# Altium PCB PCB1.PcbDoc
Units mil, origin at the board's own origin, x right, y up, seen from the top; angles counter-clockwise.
Board outline 2185.43 x 2030.28 mil, 2 copper layers (Top Layer, Bottom Layer); 55 components, 46 nets, 190 pads, 15 vias.
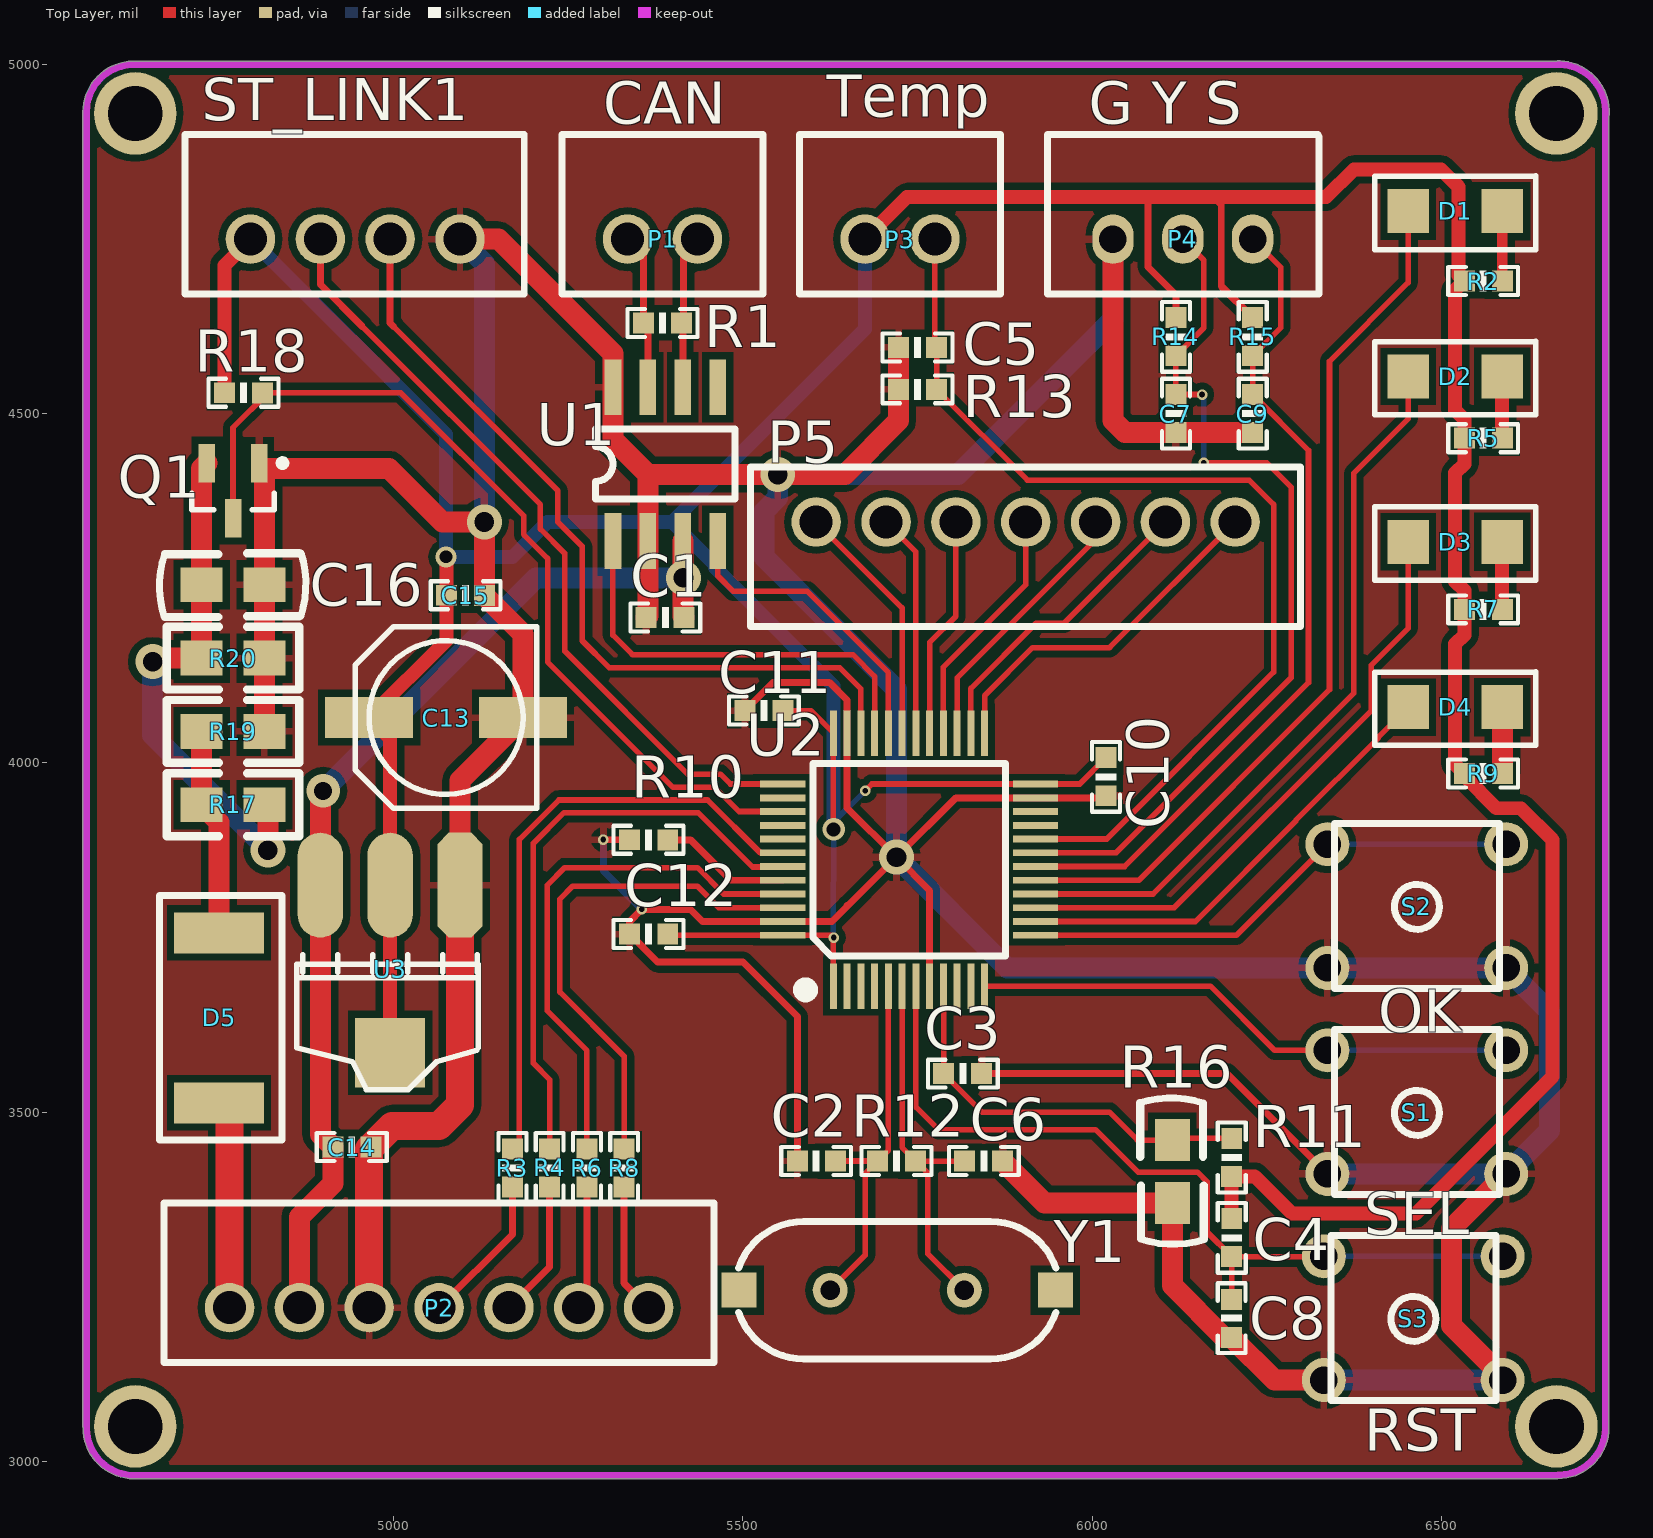
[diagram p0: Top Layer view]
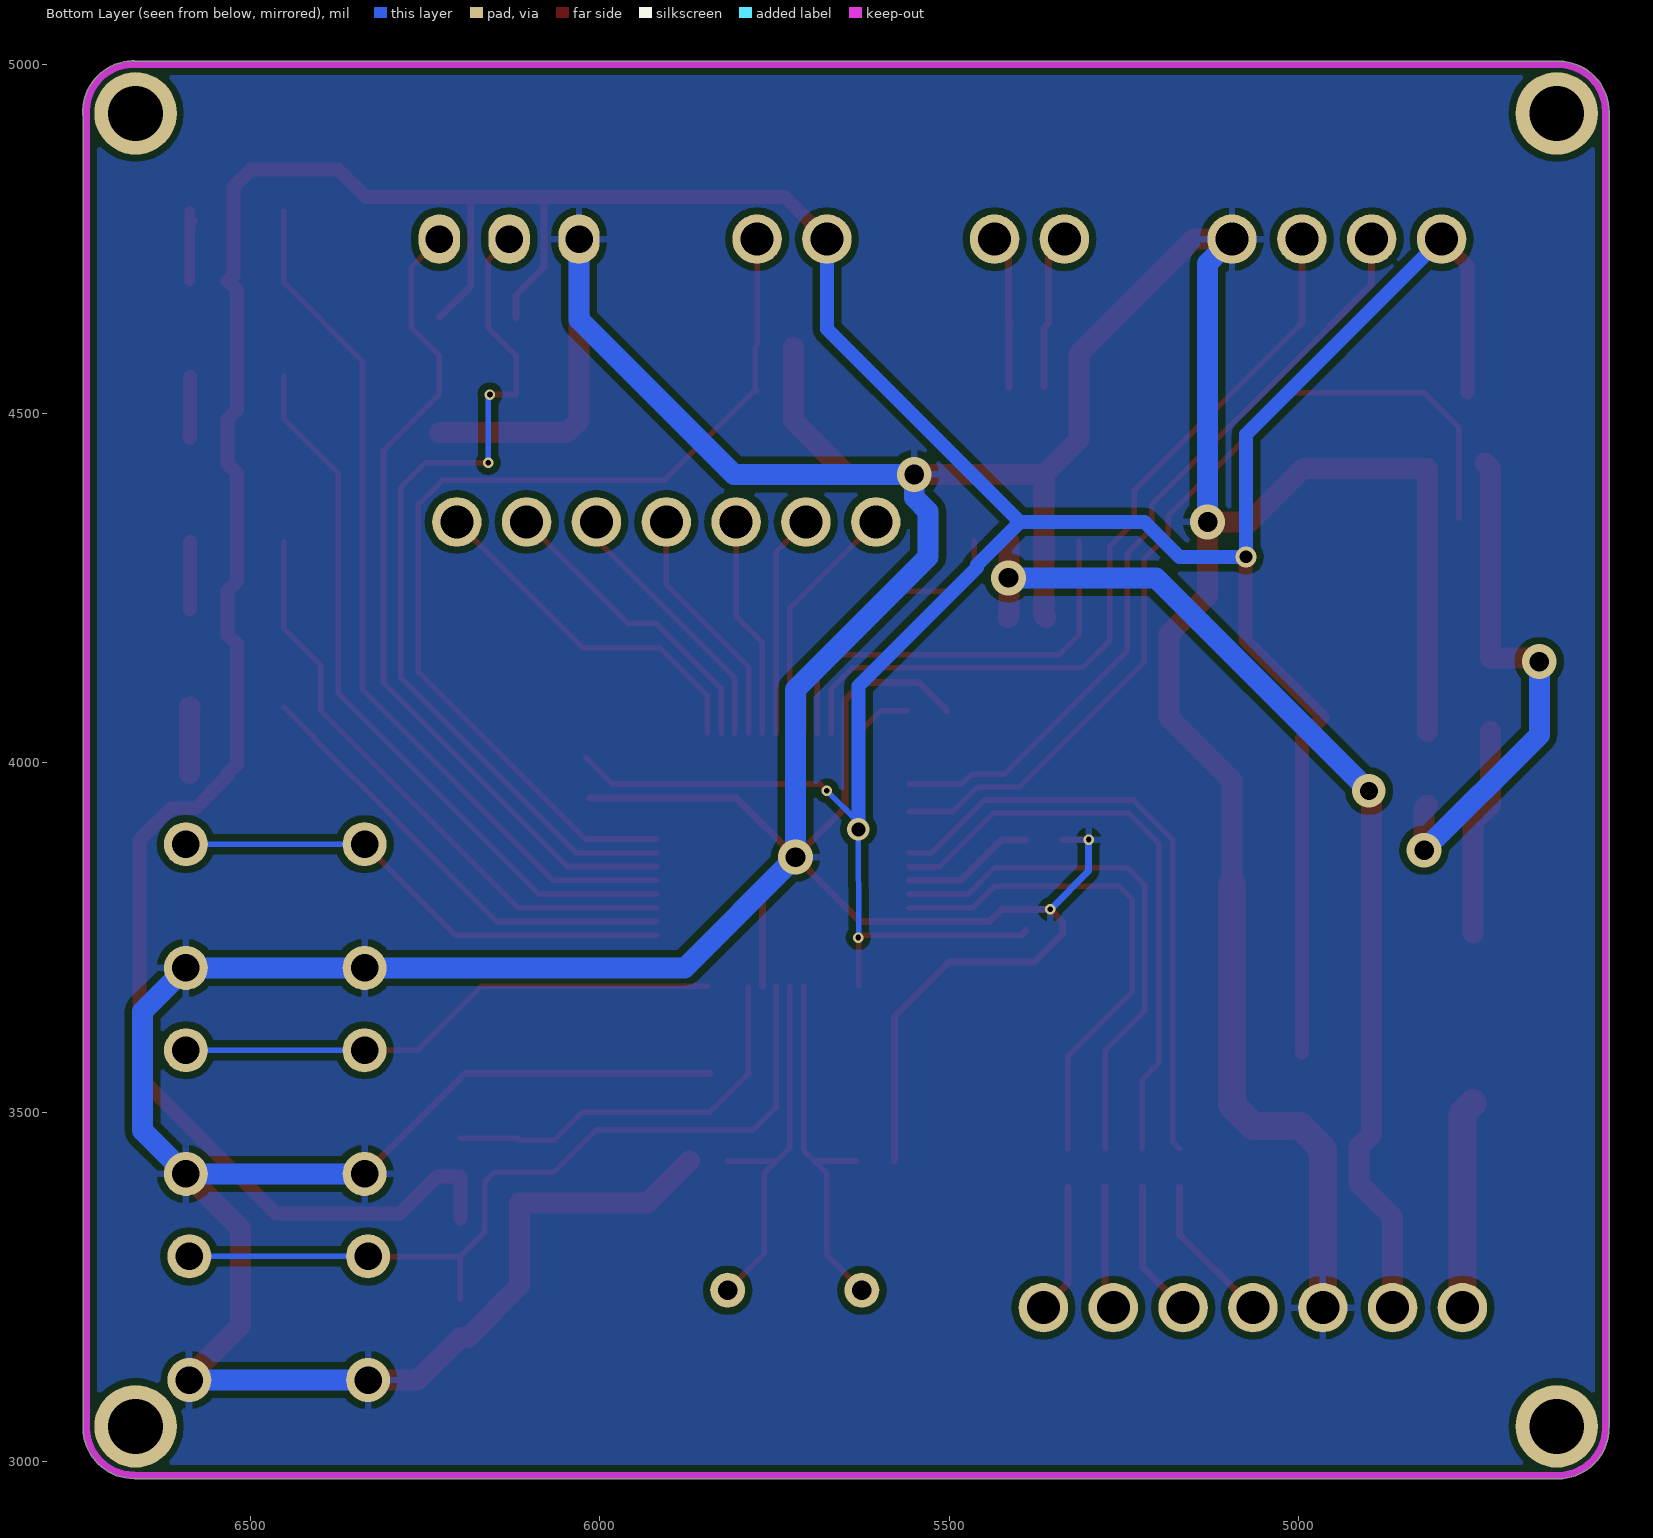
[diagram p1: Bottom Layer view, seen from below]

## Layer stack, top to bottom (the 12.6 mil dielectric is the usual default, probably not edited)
Top Layer: signal copper 1.4
Dielectric: dielectric 12.6, FR-4, Dk 4.8
Bottom Layer: signal copper 1.4

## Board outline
4555.22,3047.88 ccw(c4628.12,3047.88) 4627.86,2974.99 ccw(c4627.88,2980) 4628.94,2975.1 ccw(c4630,2980) 4630,2974.99 6665,2974.99 ccw(c6665,2980) 6666.6,2975.25 ccw(c6667.12,2980.24) 6667.12,2975.22 ccw(c6667.12,3048.12) 6740.01,3047.86 ccw(c6735,3047.88) 6740.01,3047.88 ccw(c6735,3047.88) 6739.9,3048.94 ccw(c6735,3050) 6740.02,3050 6740.02,4924.73 ccw(c6667.52,4932.36) 6740.42,4932.36 ccw(c6667.52,4932.36) 6740.02,4939.99 6740.02,4940 ccw(c6735,4940) 6739.89,4941.13 ccw(c6667.52,4932.36) 6676.85,5004.66 ccw(c6675,5000) 6675,5005.02 6673.5,5005.02 ccw(c6667.52,4932.36) 6667.77,5005.26 ccw(c6667.75,5000.25) 6666.21,5005.02 4627.88,5005.02 ccw(c4627.88,5000) 4626.31,5004.76 ccw(c4627.88,4931.88) 4554.99,4932.14 ccw(c4560,4932.12) 4554.99,4932.01 ccw(c4560,4931.88) 4554.98,4931.88 4554.98,3050 ccw(c4560,3050) 4555.25,3048.4 ccw(c4560.24,3047.88)

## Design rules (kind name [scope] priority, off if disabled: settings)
Clearance Clearance_1 [InPolygon] p1: gap=10
Clearance Clearance_U2 [InComponent('U2')] p2: gap=6
Clearance [All] p3: gap=10
ComponentClearance [All] p1 off: gap=10 collisioncheckmode=3 verticalgap=10 showdistances=FALSE
MinimumSolderMaskSliver [All] p1 off: minsoldermaskwidth=10
PolygonConnect [All] p1: connectstyle=Relief reliefconductorwidth=10 reliefentries=4 polygonreliefangle="90 Angle" airgapwidth=10
RoutingVias [All] p1: holewidth=28 width=50 viastyle="Through Hole" minholewidth=28 minwidth=50 maxholewidth=28 maxwidth=50
SilkToSilkClearance [All] p1 off: silktosilkclearance=10
SilkToSolderMaskClearance [IsPad] p1 off: minsilkscreentomaskgap=10 clearancetoexposedcopper=TRUE
SolderMaskExpansion [All] p1: expansion=4
Width [All] p1: maxlimit=50 minlimit=8 preferedwidth=10
24 further rules are at their usual default settings.

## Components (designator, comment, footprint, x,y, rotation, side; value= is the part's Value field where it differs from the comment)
C1 "Cap" 0603P 5389,4208 r180 top
C2 "Cap" 0603P 5605,3430 r0 top
C3 "Cap" 0603P 5815,3555 r180 top
C4 "Cap" 0805_C 6115,3370 r90 top
C5 "Cap" 0603P 5750,4595 r0 top
C6 "Cap" 0603P 5845,3430 r180 top
C7 "Cap" 0603P 6120,4500 r90 top
C8 "Cap" 0603P 6200,3205 r270 top
C9 "Cap" 0603P 6230,4500 r90 top
C10 "Cap" 0603P 6020,3980 r90 top
C11 "Cap" 0603P 5530,4075 r0 top
C12 "Cap" 0603P 5365,3755 r0 top
C13 "Cap Pol1" CC6.56.5 5075,4065 r0 top
C14 "Cap" 0603P 4940,3450 r0 top
C15 "Cap" 0603P 5103,4240 r180 top
C16 "Cap" 0805_C 4815,4255 r180 top
D1 "1206" 1206 6520,4790 r180 top
D2 "1206" 1206 6520,4553.33 r180 top
D3 "1206" 1206 6520,4316.67 r180 top
D4 "1206" 1206 6520,4080 r180 top
D5 "1N4007" DO-214AB 4750,3635 r90 top
P1 "CAN" 2.54_2P 5335,4750 r0 top
P2 "" 2.54_7P 4765,3220 r0 top
P3 "Temp" 2.54_2P 5675,4750 r0 top
P4 "G Y S" 2.54_3P 6030,4750 r0 top
P5 "" 2.54_7P 6205,4345 r180 top
Q1 "S9014" SOT23-3 4770,4390 r270 top
R1 "Res2" 0603P 5385,4630 r180 top
R2 "Res2" 0603P 6560,4690 r0 top
R3 "Res2" 0603P 5170,3420 r90 top
R4 "Res2" 0603P 5223.33,3420 r90 top
R5 "Res2" 0603P 6560,4465 r0 top
R6 "Res2" 0603P 5276.67,3420 r90 top
R7 "Res2" 0603P 6560,4220 r0 top
R8 "Res2" 0603P 5330,3420 r90 top
R9 "Res2" 0603P 6560,3985 r0 top
R10 "Res2" 0603P 5365,3890 r0 top
R11 "Res2" 0603P 6200,3435 r90 top
R12 "Res2" 0603P 5720,3430 r0 top
R13 "Res2" 0603P 5750,4535 r0 top
R14 "Res2" 0603P 6120,4610 r90 top
R15 "Res2" 0603P 6230,4610 r90 top
R16 "Res2" 0603P 6200,3320 r90 top
R17 "Res2" 0805_R 4815,3940 r180 top
R18 "Res2" 0603P 4785,4530 r180 top
R19 "Res2" 0805_R 4815,4045 r180 top
R20 "Res2" 0805_R 4815,4150 r180 top
S1 "SEL" "KEY 6*6" 6465,3500 r180 top
S2 "OK" "KEY 6*6" 6465,3795 r180 top
S3 "RST" "KEY 6*6" 6460,3205 r180 top
ST_LINK1 "Header 4" 2.54_4P 4795,4750 r0 top
U1 "TJA1050" SO-8 5314,4318 r90 top
U2 "STM32F103C8T6" LQFP48S 5630,3680 r90 top
U3 "AMS1117-3.3" AMS1117 5095,3825 r180 top
Y1 "8M" XTAL_US 5625,3245 r0 top

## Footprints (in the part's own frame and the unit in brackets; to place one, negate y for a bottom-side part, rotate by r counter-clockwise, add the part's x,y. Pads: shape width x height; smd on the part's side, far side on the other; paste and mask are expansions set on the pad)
2.54_2P [mm]
  round 1.8 hole 1.2: 1(0,0) 2(2.54,0)
  silkscreen extent -2.38,-2 4.92,3.8
2.54_3P [mm]
  oval 1.5x1.8 hole 1: 1(0,0) 2(2.54,0) 3(5.08,0)
  silkscreen extent -2.38,-2 7.49,3.8
2.54_4P [mm]
  round 1.8 hole 1.2: 1(0,0) 2(2.54,0) 3(5.08,0) 4(7.62,0)
  silkscreen extent -2.38,-2 9.96,3.8
2.54_7P [mm]
  round 1.8 hole 1.2: 1(0,0) 2(2.54,0) 3(5.08,0) 4(7.62,0) 5(10.16,0) 6(12.7,0) 7(15.24,0)
  silkscreen extent -2.38,-2 17.62,3.8
0603P [mil]
  rect 30x30 smd: 1(-27,0) 2(27.5,-0.06)
  silkscreen extent -50,-20 50,20
0805_C [mil]
  rect 60x50 smd: 1(0,-0.06) 2(90,-0.06)
  silkscreen extent -59,-46 150,47
0805_R [mil]
  rect 60x50 smd: 1(0,-0.06) 2(90,-0.06)
  silkscreen extent -50,-45 140,45
1206 [mm]
  rect 1.52x1.6 smd: 1(-1.71,0) 2(1.71,0)
  silkscreen extent -2.92,-1.28 2.92,1.4
AMS1117 [mil]
  oct 65x150 smd: 1(0.03,-0.06)
  oval 65x150 smd: 2(100.03,-0.06) 3(200.03,-0.06)
  rect 100x100 smd: 4(100.03,239.94)
  silkscreen extent -26,100 234,293
CC6.56.5 [mm]
  rect 3.2x1.5 smd: 1(-2.794,0) 2(2.8,0)
  silkscreen extent -3.3,-3.3 3.3,3.3
DO-214AB [mm]
  rect 1.49x3.27 smd: 1(-3.09,0) 2(3.09,0)
  silkscreen extent -4.44,-2.29 4.44,2.16
"KEY 6*6" [mm]
  round 1.6 hole 1: 1(-3.25,2.25) 1(3.25,2.25) 2(-3.25,-2.25) 2(3.25,-2.25)
  silkscreen extent -3,-3 3,3
LQFP48S [mil] "DPIN-0.5"
  rect 65x10 smd: 1(0.42,0.29) 2(0.42,-19.39) 3(0.42,-39.08) 4(0.42,-58.76) 5(0.42,-78.45) 6(0.42,-98.13) 7(0.42,-117.82) 8(0.42,-137.5) 9(0.42,-157.19) 10(0.42,-176.87) 11(0.42,-196.56) 12(0.42,-216.24) 25(362.63,-216.24) 26(362.63,-196.56) 27(362.63,-176.87) 28(362.63,-157.19) 29(362.63,-137.5) 30(362.63,-117.82) 31(362.63,-98.13) 32(362.63,-78.45) 33(362.63,-58.76) 34(362.63,-39.08) 35(362.63,-19.39) 36(362.63,0.29)
  rect 10x65 smd: 13(73.26,-289.08) 14(92.94,-289.08) 15(112.63,-289.08) 16(132.31,-289.08) 17(152,-289.08) 18(171.68,-289.08) 19(191.37,-289.08) 20(211.05,-289.08) 21(230.74,-289.08) 22(250.42,-289.08) 23(270.11,-289.08) 24(289.79,-289.08) 37(289.79,73.13) 38(270.11,73.13) 39(250.42,73.13) 40(230.74,73.13) 41(211.05,73.13) 42(191.37,73.13) 43(171.68,73.13) 44(152,73.13) 45(132.31,73.13) 46(112.63,73.13) 47(92.94,73.13) 48(73.26,73.13)
  silkscreen extent -10,-246 319,46
SO-8 [mil]
  rect 80x24 smd: 1(0,0) 2(0,-50) 3(0,-100) 4(0,-150) 5(220,-150) 6(220,-100) 7(220,-50) 8(220,0)
  silkscreen extent 60,-175 160,25, body extent -11,-172 225,21, height 64
SOT23-3 [mm] "SOT23, 3-Leads, Body 2.90x2.45mm, Pitch 0.95mm, IPC Medium Density"
  rect 1.4x0.6 smd: 1(-1,0.95) 2(-1,-0.95) 3(1,0)
  silkscreen extent -1.12,-1.5 0.7,1.93, body extent -0.7,-1.5 0.7,1.5, height 1
XTAL_US [mil]
  round 50 hole 28: 1(0,0) 2(192.13,0)
  rect 50x50 smd: ""(-130.32,0) ""(322.44,0)
  silkscreen extent -131,-98 323,98

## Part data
C1 C2 C3 C4 C5 C6 C7 C8 C9 C10 C11 C12 C14 C15 C16: "Capacitor"
C13: "Polarized Capacitor (Radial)"
D1 D2 D3 D4: library part LED0, "Typical INFRARED GaAs LED"
D5: library part "Diode 1N4007", "1 Amp General Purpose Rectifier"
P1 P3: library part "Header 2", "Header, 2-Pin"
P2 P5: library part "Header 7", "Header, 7-Pin"
P4: library part "Header 3", "Header, 3-Pin"
Q1: library part 2N3904, "NPN General Purpose Amplifier"
R1 R2 R3 R4 R5 R6 R7 R8 R9 R10 R11 R12 R13 R14 R15 R16 R17 R18 R19 R20: "Resistor"
S1 S2 S3: library part SW-PB, "Switch"
ST_LINK1: "Header, 4-Pin"
U3: library part AMS1117
Y1: library part XTAL, "Crystal Oscillator"

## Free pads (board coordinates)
  round 118.11 hole 78.74: 0(4630,3050) 0(4630,4930) 0(6665,3050) 0(6665,4930)

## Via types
v1: diameter 15, hole 8, Top Layer to Bottom Layer, 6 vias
v2: diameter 50, hole 28, Top Layer to Bottom Layer, 6 vias
v3: diameter 32, hole 20, Top Layer to Bottom Layer, 1 vias
v4: diameter 48, hole 26, Top Layer to Bottom Layer, 1 vias
v5: diameter 30, hole 18, Top Layer to Bottom Layer, 1 vias

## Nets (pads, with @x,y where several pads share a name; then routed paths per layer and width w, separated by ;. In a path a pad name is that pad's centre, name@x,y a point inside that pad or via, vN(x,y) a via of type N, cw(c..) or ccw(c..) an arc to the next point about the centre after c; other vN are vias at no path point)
3V3: C10.2 C11.2 C12.2 C13.1 C15.2 P3.1 R2.1 R5.1 R7.1 R9.1 R11.1 R14.2 R15.2 R16.2 R18.2 ST_LINK1.1 U2.1 U2.24 U2.36 U2.48 U3.2 U3.4 | length 7379.3
  Top Layer w8: C12.2@5396.68,3753.26 U2.48 5626.74,3753.26 v1(5630,3750) 5629.71,3749.71 U2.1 ; C11.2@5560,4074.94 5597.4,4074.94 U2.36 v3@5629.71,3905 ; v1(5675,3960) 5684.79,3969.79 U2.24 5982.36,3969.79 C10.2
  Top Layer w10: C12.2@5390,3759.94 C12.2@5396.68,3753.26 ; 6080,4810 6080,4710.13 6120.06,4670.06 R14.2 ; 6175,4810 6185,4800 6185,4682.56 R15.2
  Top Layer w20: R18.2 4757.5,4712.5 ST_LINK1.1 ; U3.4 U3.2 4994.97,4035.03 C13.1 5075.5,4175.5 C15.2 5075.5,4294.44 v5(5075,4294.94) ; P3.1 5735,4810 6080,4810 6175,4810 6335,4810 6375,4850 6500,4850 6525,4825 6525,4698 R2.1 6520,4677 6520,4505 6533,4492 R5.1 6533,4428 6520,4415 6520,4260 6533,4247 R7.1 6533,4183 6520,4170 6520,3998 R9.1 6533,3981.15 6579.07,3935.08 6614.28,3935.08 6659.36,3890 6659.36,3550.65 6463.71,3355 6286,3355 6233,3408 R11.1 6200,3347.56 R16.2
  Bottom Layer w8: v1@5629.71,3755 v3(5630,3905) ; v3@5630,3915 v1(5675,3960)
  Bottom Layer w20: ST_LINK1.1 5075,4470 v5@5075,4295 ; v5(5075,4294.94) 5169.94,4294.94 5220,4345 5398.64,4345 ; v3(5630,3905) 5630,3915 5630,4110 5460,4280 5460,4283.64 5398.64,4345 ; P3.1 5675,4621.36 5398.64,4345
5V0: C1.1 C14.1 P2.2 U1.3 U3.3 | length 1523.2
  Top Layer w30: P2.2 4865,3350 4913,3398 C14.1 4894.97,3468.03 U3.3 4894.97,3955.9 v4(4899,3959.94) ; U1.3 5414,4210 C1.1
  Bottom Layer w30: v4@4898,3960 v4@4899.06,3960 ; v4(4899,3959.94) v4@4899.06,3960 ; v2(5415,4265) 5204.06,4265 v4@4899.06,3960
A: P5.1 U2.25 | length 515.4
  Top Layer w8: U2.25 5846.24,4096.24 5915,4165 6025,4165 P5.1
B: P5.2 U2.26 | length 441.1
  Top Layer w8: U2.26 5826.56,4106.56 5920,4200 5960,4200 P5.2
C: P5.3 U2.27 | length 384.4
  Top Layer w8: U2.27 5806.87,4121.87 6005,4320 P5.3
CAN_RX: U1.4 U2.32 | length 438.7
  Top Layer w8: U1.4 5464,4268 5486,4246 5591.98,4246 5708.45,4129.53 U2.32
CAN_TX: U1.1 U2.33 | length 615.4
  Top Layer w8: U1.1 5314,4183 5342,4155 5657.53,4155 5688.76,4123.76 U2.33
CLK: P5.5 U2.29 | length 317.9
  Top Layer w8: U2.29 5767.5,4172.5 5805,4210 P5.5
D: R4.2 U2.43 | length 854.8
  Top Layer w8: R4.2 5223.4,3546.6 5200,3570 5200,3885 5243.94,3928.94 5436.06,3928.94 5514,3851 5556.19,3851 U2.43
DI: P5.7 U2.31 | length 353.4
  Top Layer w8: P5.7 5728.13,4221.87 U2.31
DJ: P2.6 R6.1 | length 177.8
  Top Layer w10: P2.6 5276.67,3231.67 R6.1
EN: P5.4 U2.28 | length 351.2
  Top Layer w8: U2.28 5787.19,4137.19 5905,4255 P5.4
F: R3.2 U2.42 | length 878.6
  Top Layer w8: R3.2 5180.06,3457.5 5180.06,3890.52 5236.48,3946.94 5449.35,3946.94 5524.92,3871.37 U2.42
FMQ: P2.4 R3.1 | length 216.5
  Top Layer w10: P2.4 5170,3325 R3.1
GND: C1.2 C2.1 C3.1 C4.1 C5.1 C6.1 C7.1 C8.2 C9.1 C10.1 C11.1 C12.1 C13.2 C14.2 C15.1 C16.1 P2.3 P4.1 Q1.1 R10.1 R13.1 R19.1 R20.1 S1.1 S2.1 S3.1 ST_LINK1.4 U1.2 U1.8 U2.8 U2.23 U2.35 U2.47 U3.1 | length 10858.3
  Top Layer w8: v2(5720,3865) v2@5730,3865
  Top Layer w10: v1(5300.29,3890.29) 5300.58,3890 R10.1 ; C11.1 5543,4115 5624.39,4115 5649.39,4090 U2.35 5649.39,3935.61 v2(5720,3865) ; C2.1 5578,3637 5500,3715 5378,3715 C12.1 5338,3773 5355,3790 5425,3790 5442.06,3772.94 U2.47 5627.94,3772.94 5650,3795 ; 5649.39,3795.61 5650,3795 ; U2.8 5767.5,3817.5 v2(5720,3865) ; C3.1 6193.46,3555 S1.1@6337.05,3411.42 ; C10.1@6014.89,3950.11 U2.23 5805.11,3950.11 v2(5720,3865) ; 5650,3795 v2(5720,3865)
  Top Layer w30: R19.1 R20.1 C16.1 4815,4421.77 4993.23,4421.77 5070,4345 v2(5130,4345) C15.1 5185.24,4184.76 C13.2 5094.97,3974.73 U3.1 ; ST_LINK1.4 5150,4750 5314,4586 U1.8 5314,4463 5364,4413 ; C1.2 5364,4210.56 U1.2 5364,4413 ; C5.1 R13.1 5723,4490 5646,4413 v2(5550,4413) 5364,4413 ; C6.1 5932,3370 C4.1 6115.06,3251.58 6189.14,3177.5 C8.2 6261.02,3116.42 S3.1@6332.05,3116.42 ; P4.1 6030,4490 6047,4473 C7.1 C9.1 ; S3.1@6592.95,3116.42 6515,3194.37 6515,3333.46 S1.1@6592.95,3411.42
  Top Layer w40: P2.3 4965,3447.44 C14.2 4997.56,3480 5065.06,3480 5094.97,3509.9 U3.1
  Bottom Layer w10: v1(5300.29,3890.29) 5300.29,3845 v1(5355,3790.29)
  Bottom Layer w30: ST_LINK1.4 5130,4715 v2(5130,4345) ; P4.1 6030,4635 5808,4413 v2(5550,4413) 5550,4380 5530,4360 5530,4295 5720,4105 v2(5720,3865) 5878.58,3706.42 6337.05,3706.42 6592.95,3706.42 6655,3644.37 6655,3473.46 6592.95,3411.42 S1.1@6337.05,3411.42 ; S3.1@6323.58,3116.42 6332.05,3116.42 6587.95,3116.42 S3.1@6592.95,3116.42
HH: P2.5 R4.1 | length 197.2
  Top Layer w10: P2.5 5223.33,3278.33 R4.1
KEY_OK: S2.2 U2.13 | length 727.9
  Top Layer w8: U2.13 6206.73,3753.26 S2.2@6337.05,3883.57
  Bottom Layer w8: S2.2@6337.05,3883.57 S2.2@6592.94,3883.57
KEY_SELECT: S1.2 U2.12 | length 784.8
  Top Layer w8: U2.12 6169.58,3680.42 6261.43,3588.57 S1.2@6337.05,3588.57
  Bottom Layer w8: S1.2@6337.05,3588.57 S1.2@6592.94,3588.57
LAT: P5.6 U2.30 | length 320.1
  Top Layer w8: P5.6 5747.82,4302.18 U2.30
LED0: D1.2 U2.17 | length 1265.7
  Top Layer w8: U2.17 6067,3832 6340,4105 6340,4575 6452.68,4687.68 D1.2
LED1: D2.2 U2.16 | length 1060.6
  Top Layer w8: U2.16 6087.31,3812.31 6375,4100 6375,4415 6452.68,4492.68 D2.2
LED2: D3.2 U2.15 | length 861.4
  Top Layer w8: U2.15 6117.63,3792.63 6400,4075 6400,4140 6452.68,4192.68 D3.2
LED3: D4.2 U2.14 | length 662.1
  Top Layer w8: U2.14 6147.94,3772.94 6291.55,3916.55 6291.55,3917.42 6410,4035.87 6410,4037.32 D4.2
M: R6.2 U2.45 | length 763.8
  Top Layer w8: R6.2 5276.73,3588.27 5220,3645 5220,3825 5245,3850 5435,3850 5472.69,3812.31 U2.45
NetC3_2: C3.2 C4.2 R11.2 U2.9 | length 577.3
  Top Layer w8: U2.9@5787.5,3679.37 C3.2 5842.56,3500 6025,3500 6065,3460 C4.2 6117.56,3462.5 R11.2
NetC16_2: C16.2 Q1.2 R17.1 R20.2 | length 760
  Top Layer w30: v2(4655,4145) 4660.06,4150.06 R20.2 C16.2 4725,4421.77 Q1.2 ; R17.1 4820,3935.06 v2(4820,3875)
  Bottom Layer w30: v2(4655,4145) 4655,4040 v2(4820,3875)
NetD1_1: D1.1 R2.2 | length 106.3
  Top Layer w15: D1.1@6582.94,4775.61 D1.1@6587.32,4780 ; D1.1 D1.1@6587.32,4780 ; R2.2 6587.32,4690.11 D1.1@6587.32,4780
NetD2_1: D2.1 R5.2 | length 88.5
  Top Layer w20: D2.1 6587.32,4465.11 R5.2
NetD3_1: D3.1 R7.2 | length 96.8
  Top Layer w20: D3.1 6587.32,4220.11 R7.2
NetD4_1: D4.1 R9.2 | length 95.1
  Top Layer w30: D4.1 6587.5,4079.82 R9.2
NetD5_2: D5.2 R17.2 R19.2 | length 298.8
  Top Layer w30: R19.2 R17.2 4750,3915.06 D5.2
NetP1_1: P1.1 R1.2 U1.7 | length 224
  Top Layer w10: P1.1 5357.5,4727.5 R1.2 5364,4623.56 U1.7
NetP1_2: P1.2 R1.1 U1.6 | length 222.4
  Top Layer w10: U1.6 5414,4628 R1.1 5415,4633 5415,4730 P1.2
NetR10_2: R10.2 U2.44 | length 190.9
  Top Layer w10: R10.2@5390,3889.94 5425.06,3889.94 5483,3832 U2.44
OSC_IN: C2.2 R12.1 U2.5 Y1.1 | length 530.5
  Top Layer w8: Y1.1 5675,3295 5675,3412 R12.1 ; C2.2 5632.56,3430 R12.1 ; U2.5 5708.45,3445.45 R12.1
OSC_OUT: C6.2 R12.2 U2.6 Y1.2 | length 542.3
  Top Layer w8: U2.6 5728.13,3449.3 R12.2 ; Y1.2 5765,3297.13 5765,3412.44 R12.2 ; C6.2 5817.37,3429.94 R12.2
R: R8.2 U2.46 | length 735
  Top Layer w8: R8.2 5330.06,3579.94 5238,3672 5238,3805.08 5256.46,3823.54 5434.77,3823.54 5465.69,3792.63 U2.46
RESET: C8.1 R16.1 S3.2 U2.7 | length 1205.5
  Top Layer w8: U2.7 5747.82,3507.18 5780,3475 6005,3475 6066,3414 6151,3414 6165,3400 6165,3328 R16.1 ; C8.1 R16.1 ; S3.2@6332.05,3293.57 6331.47,3293 R16.1
  Bottom Layer w8: S3.2@6332.05,3293.57 6337.05,3293.57 S3.2@6587.94,3293.57
RG: P2.7 R8.1 | length 187.5
  Top Layer w10: R8.1 5330,3255 P2.7
S: C9.2 P4.3 R15.1 U2.18 | length 1201.3
  Top Layer w8: U2.18 6046.68,3851.68 6310,4115 6310,4447.56 C9.2 6230,4527.56 R15.1 6270,4623 6270,4710 P4.3
TCK: ST_LINK1.2 U2.37 | length 1125.6
  Top Layer w8: 4955,4625 5210,4370 5210,4335 5245,4300 5245,4160 5421,3984 5467.87,3984 5482.08,3969.79 U2.37
  Top Layer w10: ST_LINK1.2 4895,4685 4955,4625
TEMP: C5.2 P3.2 R13.2 U2.20 | length 1444.5
  Top Layer w8: P3.2@5775,4745 5775,4597.44 C5.2 R13.2 ; R13.2@5775.57,4533 R13.2 ; U2.20 6021.05,3891.05 6260,4130 6260,4370 6225,4405 5907.44,4405 R13.2
TMS: ST_LINK1.3 U2.34 | length 1179.9
  Top Layer w8: 5000,4625 5235,4390 5235,4345 5270,4310 5270,4175 5309,4136 5639,4136 5669.08,4105.92 U2.34
  Top Layer w10: ST_LINK1.3 4995,4630 5000,4625
TR: D5.1 P2.1 | length 299.6
  Top Layer w40: D5.1 4765,3498.35 P2.1
Y: C7.2 P4.2 R14.1 U2.19 | length 1269.6
  Top Layer w8: U2.19 6034.37,3871.37 6285,4122 6285,4395 6250,4430 v1(6160,4430) ; C7.2@6120,4527.56 R14.1 6160,4623 6160,4720 P4.2 ; C7.2 v1(6157.5,4527.5)
  Bottom Layer w8: v1(6157.5,4527.5) 6160,4525 v1(6160,4430)
ZERO: Q1.3 R18.1 U2.39 | length 1287.9
  Top Layer w8: Q1.3 4770,4480.06 4820,4530.06 5009.94,4530.06 5186,4354 5186,4327.13 5220.42,4292.71 5220.42,4144.58 5400,3965 5460,3965 5494.58,3930.42 U2.39
pads on no net: U1.5 U2.2 U2.3 U2.4 U2.10 U2.11 U2.21 U2.22 U2.38 U2.40 U2.41 Y1.

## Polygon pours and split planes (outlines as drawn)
GND on Top Layer "Top Layer-No Net" (solid, pour order 2): 4627.88,4999.76 4603.12,4975 4575,4975 4575,4946.88 4560,4931.88 4560.24,4931.65 4560.24,3047.88 4560.24,3019.76 4585,2995 4600,2980 4627.88,2980 6665,2980 6690,3005 6720,3005 6720,3025 6735,3040 6735,3065 6735,4940 6720,4955 6720,4975 6700,4975 6675,5000
GND on Bottom Layer "Top Layer-No Net" (solid, pour order 4): 4560,4932.12 4560,3050 4560,3020 4585,2995 4600,2980 4627.88,2980 6665,2980 6690,3005 6720,3005 6720,3032.88 6735,3047.88 6735,4915 6735,4960 6715,4980 6695,5000 6665,5000 4627.88,5000 4612.88,4985 4580,4985

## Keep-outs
Keep-Out Layer:
  lines w10: 4560,3050 4560,4931.88 ; 4560,4932.12 cw(c4627.88,4931.88) 4627.88,4999.76 ; 4560.24,3047.88 ccw(c4628.12,3047.88) 4627.88,2980 ; 4627.88,5000 6675,5000 ; 4630,2980 6665,2980 ; 6667.12,2980.24 ccw(c6667.12,3048.12) 6735,3047.88 ; 6667.75,5000.25 cw(c6667.52,4932.36) 6735,4925 ; 6735,3050 6735,4940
